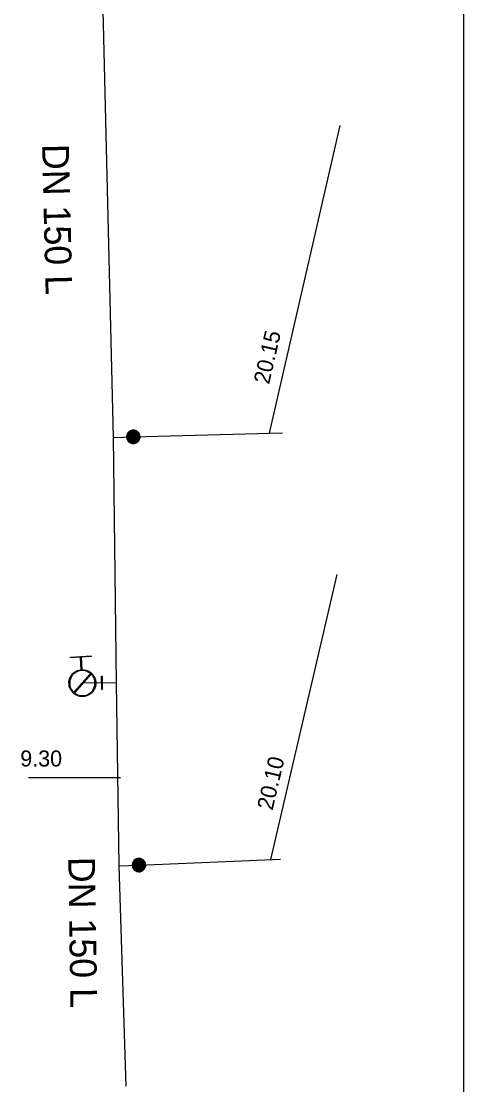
# Model space of a CAD drawing. Extents: x -820257 to -819974, y -1070894 to -1070484.
# Drawn here: x -820008.7 to -819975.6, y -1070745.2 to -1070665.6 of the extents above; entities that cross this region are included whole.
import ezdxf

# ---------------------------------------------------------------- set-up
doc = ezdxf.new("R2010")
doc.units = 0
for name, color, linetype in [('Default', 7, 'Continuous'), ('Hyd-odbočka', 7, 'Continuous'), ('Hyd-šoupě', 7, 'Continuous'), ('Hydrant', 7, 'Continuous'), ('Oměrka vodovodu', 7, 'Continuous'), ('Oměrka-text', 7, 'Continuous'), ('Přípojka vodovodu', 7, 'Continuous'), ('Přípojkový uzávěr', 7, 'Continuous'), ('Roz-řad', 7, 'Continuous'), ('Roz-řad-popis základní', 7, 'Continuous')]:
    doc.layers.add(name, color=color, linetype=linetype)

msp = doc.modelspace()

# ---------------------------------------------------------------- linework, layer by layer
at = {"layer": 'Default'}
msp.add_line((-819975.603, -1070893.932), (-819975.603, -1070484.403), dxfattribs=at)
at = {"layer": 'Hyd-odbočka'}
msp.add_line((-820001.582, -1070715.112), (-820004.106, -1070715.131), dxfattribs=at)
at = {"layer": 'Hyd-šoupě'}
msp.add_lwpolyline([(-820002.635, -1070714.62), (-820002.627, -1070715.62), (-820002.658, -1070715.621), (-820002.666, -1070714.621), (-820002.635, -1070714.62)], dxfattribs=at)
at = {"layer": 'Hydrant'}
for points in [[(-820004.198, -1070714.135), (-820004.254, -1070713.199), (-820005.003, -1070713.244), (-820005.006, -1070713.181), (-820003.447, -1070713.088), (-820003.443, -1070713.15), (-820004.192, -1070713.195), (-820004.135, -1070714.131)], [(-820004.752, -1070715.814), (-820003.506, -1070714.408)], [(-820003.461, -1070714.448), (-820004.707, -1070715.856)]]:
    msp.add_lwpolyline(points, dxfattribs=at)
for points in [[(-820004.135, -1070714.131), (-820003.899, -1070714.124), (-820003.668, -1070714.232), (-820003.422, -1070714.346), (-820003.273, -1070714.578), (-820003.124, -1070714.81), (-820003.108, -1070715.071), (-820003.093, -1070715.33), (-820003.21, -1070715.576), (-820003.327, -1070715.822), (-820003.557, -1070715.968), (-820003.787, -1070716.114), (-820004.046, -1070716.129), (-820004.306, -1070716.145), (-820004.551, -1070716.027), (-820004.797, -1070715.91), (-820004.943, -1070715.68), (-820005.089, -1070715.45), (-820005.105, -1070715.191), (-820005.12, -1070714.93), (-820005, -1070714.682), (-820004.88, -1070714.434), (-820004.65, -1070714.291), (-820004.435, -1070714.157), (-820004.198, -1070714.135)], [(-820003.506, -1070714.408), (-820003.593, -1070714.337), (-820003.695, -1070714.288), (-820003.927, -1070714.181), (-820004.163, -1070714.195), (-820004.399, -1070714.209), (-820004.616, -1070714.344), (-820004.833, -1070714.478), (-820004.945, -1070714.71), (-820005.057, -1070714.942), (-820005.042, -1070715.187), (-820005.028, -1070715.431), (-820004.889, -1070715.646), (-820004.831, -1070715.74), (-820004.752, -1070715.814)], [(-820004.707, -1070715.856), (-820004.624, -1070715.923), (-820004.524, -1070715.97), (-820004.294, -1070716.081), (-820004.05, -1070716.067), (-820003.806, -1070716.052), (-820003.591, -1070715.915), (-820003.375, -1070715.778), (-820003.265, -1070715.548), (-820003.156, -1070715.318), (-820003.171, -1070715.075), (-820003.185, -1070714.829), (-820003.326, -1070714.612), (-820003.386, -1070714.52), (-820003.461, -1070714.448)]]:
    msp.add_open_spline(points, degree=3, dxfattribs=at)
at = {"layer": 'Oměrka vodovodu'}
for p, q in [((-819990.119, -1070696.44), (-819984.831, -1070673.427)), ((-819990.032, -1070728.327), (-819985.074, -1070707.001)), ((-820008.144, -1070722.19), (-820001.245, -1070722.19))]:
    msp.add_line(p, q, dxfattribs=at)
at = {"layer": 'Přípojka vodovodu'}
for points in [[(-820001.798, -1070696.757), (-820000.299, -1070696.716), (-819989.146, -1070696.414)], [(-820001.375, -1070728.801), (-819999.876, -1070728.738), (-819989.29, -1070728.296)]]:
    msp.add_lwpolyline(points, dxfattribs=at)
at = {"layer": 'Přípojkový uzávěr'}
for points in [[(-820000.313, -1070696.217), (-820000.187, -1070696.213), (-820000.065, -1070696.275), (-819999.944, -1070696.336), (-819999.873, -1070696.454), (-819999.802, -1070696.573), (-819999.799, -1070696.704), (-819999.795, -1070696.833), (-819999.858, -1070696.954), (-819999.921, -1070697.075), (-820000.038, -1070697.144), (-820000.155, -1070697.213), (-820000.286, -1070697.216), (-820000.415, -1070697.22), (-820000.536, -1070697.157), (-820000.657, -1070697.095), (-820000.726, -1070696.978), (-820000.795, -1070696.861), (-820000.799, -1070696.731), (-820000.802, -1070696.6), (-820000.738, -1070696.478), (-820000.674, -1070696.356), (-820000.557, -1070696.288), (-820000.439, -1070696.22), (-820000.313, -1070696.217)], [(-820000.311, -1070696.264), (-820000.426, -1070696.267), (-820000.532, -1070696.328), (-820000.639, -1070696.389), (-820000.697, -1070696.5), (-820000.755, -1070696.611), (-820000.752, -1070696.729), (-820000.748, -1070696.847), (-820000.686, -1070696.953), (-820000.624, -1070697.059), (-820000.514, -1070697.116), (-820000.404, -1070697.173), (-820000.287, -1070697.17), (-820000.169, -1070697.166), (-820000.062, -1070697.104), (-819999.956, -1070697.041), (-819999.899, -1070696.932), (-819999.843, -1070696.823), (-819999.846, -1070696.705), (-819999.849, -1070696.586), (-819999.913, -1070696.479), (-819999.978, -1070696.371), (-820000.088, -1070696.316), (-820000.197, -1070696.261), (-820000.311, -1070696.264)], [(-820000.311, -1070696.298), (-820000.205, -1070696.295), (-820000.103, -1070696.346), (-820000.002, -1070696.397), (-819999.942, -1070696.497), (-819999.883, -1070696.596), (-819999.88, -1070696.706), (-819999.877, -1070696.815), (-819999.929, -1070696.916), (-819999.981, -1070697.017), (-820000.08, -1070697.075), (-820000.179, -1070697.132), (-820000.288, -1070697.135), (-820000.396, -1070697.138), (-820000.498, -1070697.086), (-820000.599, -1070697.033), (-820000.657, -1070696.935), (-820000.715, -1070696.837), (-820000.717, -1070696.728), (-820000.72, -1070696.619), (-820000.667, -1070696.516), (-820000.614, -1070696.414), (-820000.515, -1070696.357), (-820000.416, -1070696.301), (-820000.311, -1070696.298)], [(-820000.31, -1070696.342), (-820000.466, -1070696.346), (-820000.572, -1070696.459), (-820000.678, -1070696.572), (-820000.674, -1070696.727), (-820000.669, -1070696.883), (-820000.557, -1070696.989), (-820000.444, -1070697.096), (-820000.29, -1070697.092), (-820000.133, -1070697.087), (-820000.026, -1070696.975), (-819999.92, -1070696.862), (-819999.924, -1070696.707), (-819999.928, -1070696.551), (-820000.04, -1070696.444), (-820000.152, -1070696.338), (-820000.31, -1070696.342)], [(-820000.309, -1070696.388), (-820000.171, -1070696.384), (-820000.073, -1070696.477), (-819999.975, -1070696.571), (-819999.972, -1070696.707), (-819999.968, -1070696.843), (-820000.061, -1070696.942), (-820000.155, -1070697.04), (-820000.291, -1070697.044), (-820000.428, -1070697.047), (-820000.526, -1070696.954), (-820000.624, -1070696.861), (-820000.628, -1070696.725), (-820000.631, -1070696.588), (-820000.538, -1070696.49), (-820000.445, -1070696.391), (-820000.309, -1070696.388)], [(-820000.308, -1070696.427), (-820000.428, -1070696.43), (-820000.51, -1070696.517), (-820000.591, -1070696.604), (-820000.588, -1070696.724), (-820000.585, -1070696.843), (-820000.498, -1070696.925), (-820000.412, -1070697.007), (-820000.292, -1070697.004), (-820000.172, -1070697.001), (-820000.09, -1070696.914), (-820000.008, -1070696.827), (-820000.011, -1070696.708), (-820000.014, -1070696.588), (-820000.101, -1070696.506), (-820000.187, -1070696.424), (-820000.308, -1070696.427)], [(-820000.306, -1070696.467), (-820000.201, -1070696.464), (-820000.126, -1070696.535), (-820000.052, -1070696.606), (-820000.049, -1070696.71), (-820000.046, -1070696.814), (-820000.117, -1070696.889), (-820000.188, -1070696.964), (-820000.292, -1070696.967), (-820000.395, -1070696.969), (-820000.471, -1070696.898), (-820000.546, -1070696.827), (-820000.549, -1070696.724), (-820000.551, -1070696.62), (-820000.481, -1070696.545), (-820000.41, -1070696.47), (-820000.306, -1070696.467)], [(-820000.305, -1070696.513), (-820000.389, -1070696.515), (-820000.447, -1070696.576), (-820000.505, -1070696.637), (-820000.502, -1070696.722), (-820000.5, -1070696.806), (-820000.439, -1070696.864), (-820000.378, -1070696.922), (-820000.294, -1070696.919), (-820000.21, -1070696.917), (-820000.152, -1070696.856), (-820000.094, -1070696.795), (-820000.096, -1070696.711), (-820000.098, -1070696.626), (-820000.159, -1070696.569), (-820000.22, -1070696.511), (-820000.305, -1070696.513)], [(-820000.304, -1070696.548), (-820000.233, -1070696.546), (-820000.183, -1070696.594), (-820000.133, -1070696.641), (-820000.131, -1070696.712), (-820000.129, -1070696.782), (-820000.177, -1070696.832), (-820000.225, -1070696.883), (-820000.295, -1070696.885), (-820000.365, -1070696.886), (-820000.415, -1070696.839), (-820000.466, -1070696.791), (-820000.468, -1070696.721), (-820000.47, -1070696.65), (-820000.422, -1070696.6), (-820000.374, -1070696.55), (-820000.304, -1070696.548)], [(-820000.303, -1070696.592), (-820000.354, -1070696.593), (-820000.39, -1070696.631), (-820000.425, -1070696.668), (-820000.424, -1070696.72), (-820000.422, -1070696.772), (-820000.385, -1070696.807), (-820000.347, -1070696.843), (-820000.296, -1070696.842), (-820000.244, -1070696.84), (-820000.208, -1070696.803), (-820000.172, -1070696.765), (-820000.174, -1070696.713), (-820000.175, -1070696.662), (-820000.213, -1070696.626), (-820000.25, -1070696.59), (-820000.303, -1070696.592)], [(-820000.301, -1070696.639), (-820000.268, -1070696.638), (-820000.245, -1070696.66), (-820000.222, -1070696.681), (-820000.221, -1070696.715), (-820000.22, -1070696.747), (-820000.242, -1070696.77), (-820000.264, -1070696.794), (-820000.297, -1070696.795), (-820000.329, -1070696.796), (-820000.353, -1070696.773), (-820000.376, -1070696.751), (-820000.377, -1070696.719), (-820000.378, -1070696.686), (-820000.356, -1070696.663), (-820000.334, -1070696.639), (-820000.301, -1070696.639)], [(-820000.3, -1070696.67), (-820000.32, -1070696.67), (-820000.333, -1070696.684), (-820000.347, -1070696.698), (-820000.346, -1070696.718), (-820000.346, -1070696.737), (-820000.331, -1070696.751), (-820000.317, -1070696.764), (-820000.298, -1070696.764), (-820000.278, -1070696.763), (-820000.265, -1070696.749), (-820000.252, -1070696.735), (-820000.252, -1070696.715), (-820000.253, -1070696.695), (-820000.267, -1070696.682), (-820000.28, -1070696.669), (-820000.3, -1070696.67)], [(-819999.898, -1070728.239), (-819999.772, -1070728.234), (-819999.65, -1070728.293), (-819999.527, -1070728.353), (-819999.455, -1070728.47), (-819999.382, -1070728.587), (-819999.377, -1070728.718), (-819999.371, -1070728.848), (-819999.432, -1070728.969), (-819999.493, -1070729.091), (-819999.609, -1070729.162), (-819999.726, -1070729.233), (-819999.856, -1070729.238), (-819999.985, -1070729.244), (-820000.107, -1070729.183), (-820000.229, -1070729.122), (-820000.3, -1070729.006), (-820000.37, -1070728.89), (-820000.376, -1070728.76), (-820000.381, -1070728.629), (-820000.319, -1070728.506), (-820000.257, -1070728.383), (-820000.141, -1070728.314), (-820000.024, -1070728.244), (-819999.898, -1070728.239)], [(-819999.896, -1070728.286), (-820000.01, -1070728.291), (-820000.116, -1070728.353), (-820000.222, -1070728.416), (-820000.278, -1070728.528), (-820000.334, -1070728.639), (-820000.329, -1070728.758), (-820000.324, -1070728.876), (-820000.26, -1070728.981), (-820000.196, -1070729.086), (-820000.086, -1070729.141), (-819999.975, -1070729.196), (-819999.858, -1070729.191), (-819999.74, -1070729.186), (-819999.634, -1070729.122), (-819999.529, -1070729.058), (-819999.474, -1070728.948), (-819999.419, -1070728.838), (-819999.424, -1070728.72), (-819999.429, -1070728.602), (-819999.495, -1070728.495), (-819999.561, -1070728.389), (-819999.671, -1070728.335), (-819999.782, -1070728.281), (-819999.896, -1070728.286)], [(-819999.894, -1070728.32), (-819999.788, -1070728.316), (-819999.686, -1070728.365), (-819999.584, -1070728.415), (-819999.523, -1070728.513), (-819999.462, -1070728.612), (-819999.458, -1070728.722), (-819999.453, -1070728.83), (-819999.504, -1070728.932), (-819999.555, -1070729.034), (-819999.652, -1070729.093), (-819999.75, -1070729.153), (-819999.859, -1070729.157), (-819999.968, -1070729.162), (-820000.07, -1070729.111), (-820000.172, -1070729.06), (-820000.231, -1070728.963), (-820000.29, -1070728.865), (-820000.295, -1070728.757), (-820000.299, -1070728.647), (-820000.248, -1070728.544), (-820000.196, -1070728.441), (-820000.098, -1070728.383), (-820000, -1070728.324), (-819999.894, -1070728.32)], [(-819999.893, -1070728.364), (-820000.049, -1070728.37), (-820000.153, -1070728.485), (-820000.257, -1070728.599), (-820000.251, -1070728.755), (-820000.244, -1070728.91), (-820000.13, -1070729.015), (-820000.016, -1070729.12), (-819999.862, -1070729.113), (-819999.706, -1070729.107), (-819999.6, -1070728.993), (-819999.495, -1070728.879), (-819999.502, -1070728.723), (-819999.508, -1070728.568), (-819999.622, -1070728.463), (-819999.735, -1070728.357), (-819999.893, -1070728.364)], [(-819999.891, -1070728.41), (-819999.754, -1070728.404), (-819999.655, -1070728.496), (-819999.555, -1070728.588), (-819999.549, -1070728.724), (-819999.544, -1070728.86), (-819999.636, -1070728.96), (-819999.728, -1070729.06), (-819999.864, -1070729.065), (-820000, -1070729.071), (-820000.1, -1070728.979), (-820000.199, -1070728.887), (-820000.205, -1070728.751), (-820000.211, -1070728.615), (-820000.119, -1070728.515), (-820000.028, -1070728.415), (-819999.891, -1070728.41)], [(-819999.889, -1070728.449), (-820000.009, -1070728.454), (-820000.09, -1070728.542), (-820000.171, -1070728.63), (-820000.166, -1070728.75), (-820000.161, -1070728.869), (-820000.073, -1070728.95), (-819999.985, -1070729.031), (-819999.865, -1070729.026), (-819999.746, -1070729.021), (-819999.665, -1070728.933), (-819999.584, -1070728.845), (-819999.589, -1070728.726), (-819999.594, -1070728.606), (-819999.681, -1070728.525), (-819999.769, -1070728.444), (-819999.889, -1070728.449)], [(-819999.887, -1070728.489), (-819999.782, -1070728.484), (-819999.707, -1070728.555), (-819999.631, -1070728.625), (-819999.627, -1070728.729), (-819999.622, -1070728.832), (-819999.692, -1070728.908), (-819999.762, -1070728.984), (-819999.866, -1070728.988), (-819999.969, -1070728.993), (-820000.046, -1070728.923), (-820000.122, -1070728.853), (-820000.126, -1070728.749), (-820000.13, -1070728.646), (-820000.061, -1070728.569), (-819999.992, -1070728.493), (-819999.887, -1070728.489)], [(-819999.885, -1070728.535), (-819999.97, -1070728.539), (-820000.026, -1070728.6), (-820000.083, -1070728.662), (-820000.08, -1070728.747), (-820000.076, -1070728.831), (-820000.014, -1070728.888), (-819999.953, -1070728.945), (-819999.868, -1070728.941), (-819999.784, -1070728.938), (-819999.727, -1070728.876), (-819999.67, -1070728.814), (-819999.674, -1070728.73), (-819999.677, -1070728.645), (-819999.739, -1070728.588), (-819999.801, -1070728.532), (-819999.885, -1070728.535)], [(-819999.884, -1070728.57), (-819999.814, -1070728.567), (-819999.763, -1070728.614), (-819999.711, -1070728.661), (-819999.709, -1070728.731), (-819999.706, -1070728.801), (-819999.753, -1070728.852), (-819999.8, -1070728.903), (-819999.87, -1070728.906), (-819999.94, -1070728.909), (-819999.991, -1070728.862), (-820000.042, -1070728.815), (-820000.045, -1070728.745), (-820000.048, -1070728.675), (-820000.001, -1070728.624), (-819999.954, -1070728.573), (-819999.884, -1070728.57)], [(-819999.882, -1070728.614), (-819999.934, -1070728.616), (-819999.969, -1070728.654), (-820000.003, -1070728.692), (-820000.001, -1070728.744), (-819999.999, -1070728.795), (-819999.961, -1070728.831), (-819999.923, -1070728.866), (-819999.872, -1070728.863), (-819999.819, -1070728.861), (-819999.784, -1070728.823), (-819999.749, -1070728.785), (-819999.751, -1070728.733), (-819999.754, -1070728.682), (-819999.791, -1070728.647), (-819999.829, -1070728.611), (-819999.882, -1070728.614)], [(-819999.88, -1070728.661), (-819999.847, -1070728.659), (-819999.824, -1070728.681), (-819999.8, -1070728.702), (-819999.799, -1070728.735), (-819999.797, -1070728.768), (-819999.819, -1070728.791), (-819999.84, -1070728.815), (-819999.874, -1070728.817), (-819999.906, -1070728.818), (-819999.93, -1070728.796), (-819999.954, -1070728.774), (-819999.955, -1070728.742), (-819999.956, -1070728.709), (-819999.934, -1070728.685), (-819999.912, -1070728.662), (-819999.88, -1070728.661)], [(-819999.879, -1070728.692), (-819999.898, -1070728.693), (-819999.911, -1070728.707), (-819999.924, -1070728.721), (-819999.924, -1070728.741), (-819999.923, -1070728.76), (-819999.909, -1070728.773), (-819999.894, -1070728.786), (-819999.875, -1070728.785), (-819999.855, -1070728.785), (-819999.842, -1070728.77), (-819999.829, -1070728.756), (-819999.83, -1070728.737), (-819999.831, -1070728.717), (-819999.845, -1070728.704), (-819999.859, -1070728.691), (-819999.879, -1070728.692)]]:
    msp.add_open_spline(points, degree=3, dxfattribs=at)
at = {"layer": 'Roz-řad'}
for points in [[(-820002.616, -1070661.467), (-820002.619, -1070662.727), (-820001.798, -1070696.757), (-820001.582, -1070715.112)], [(-820001.582, -1070715.112), (-820001.375, -1070728.801), (-820000.867, -1070745.267)]]:
    msp.add_lwpolyline(points, dxfattribs=at)

# ---------------------------------------------------------------- texts
at = {"layer": 'Oměrka-text'}
for s, rotation, p in [('20.15', 77.05904, (-819990.153, -1070692.842)), ('20.10', 76.91202, (-819989.896, -1070724.701))]:
    msp.add_text(s, height=1.2, rotation=rotation, dxfattribs=at).set_placement(p)
msp.add_text(' 9.30', height=1.2, dxfattribs=at).set_placement((-820009.194, -1070721.37))
at = {"layer": 'Roz-řad-popis základní'}
for rotation, p in [(271.38203, (-820007.12, -1070674.839)), (270.86631, (-820005.166, -1070728.141))]:
    msp.add_text('DN 150 L', height=2, rotation=rotation, dxfattribs=at).set_placement(p)

doc.saveas('drawing.dxf')
